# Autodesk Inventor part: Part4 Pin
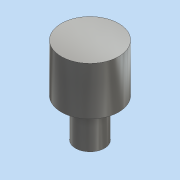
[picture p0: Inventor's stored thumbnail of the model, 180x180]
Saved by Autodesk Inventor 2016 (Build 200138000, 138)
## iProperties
Created: 2015-11
Part Number: Part4 Pin
Material: Gold
Document SubType Name: Modeling
Designer: SanPer86
Density: 19.3 g/cm^3
Appearance: Sky Blue Dark
Mass: 0.00605759 g
Surface Area: 0.0277642 cm^2
Volume: 0.000313865 cm^3
Author: SanPer86
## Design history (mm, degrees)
sketch "Sketch1"
  geometry: C1 r 0.373 at (0, 0); 1 further point
  constraints: 1 centre point
  dimensions: "d8" = 0.745 diameter of C1
extrude "Extrusion1" new body sketch "Sketch1" distance "d9" = 0.625; taper "d10" = 0 deg
sketch "Sketch2"
  geometry: C1 r 0.188 at (0, 0); 1 further point
  constraints: 1 centre point, 1 coincident
  dimensions: "d11" = 0.375 diameter of C1
extrude "Extrusion2" join sketch "Sketch2" distance "d12" = 0.5; taper "d13" = 0 deg
body "Solid2"
